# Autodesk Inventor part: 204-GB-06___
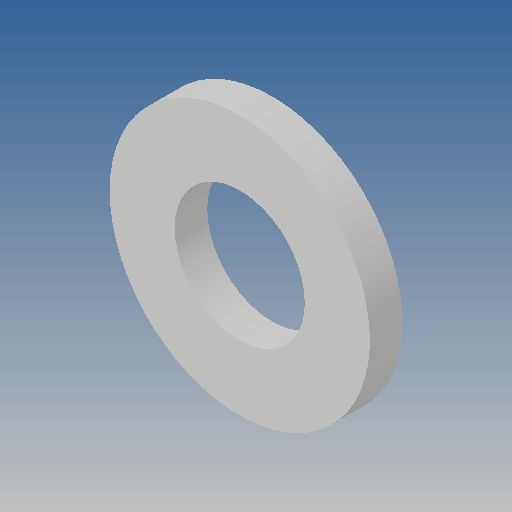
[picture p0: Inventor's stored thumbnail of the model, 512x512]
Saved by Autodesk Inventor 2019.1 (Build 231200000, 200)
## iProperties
Created: 2010-06
Part Number: 204-GB-06___
Material: Ogólny
Document SubType Name: Modeling
Designer: CADENGINEERING4
Density: 1 g/cm^3
Appearance: Domyślna
Author: CADENGINEERING4
Revision Number: ANY
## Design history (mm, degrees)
feature "NONE"
node "Bryła1"
